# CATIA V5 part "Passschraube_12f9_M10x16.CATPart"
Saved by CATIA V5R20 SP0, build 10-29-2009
Part number: Passschraube_12f9_M10x30
Bounding box of the stored display mesh (mm): x -9 to 9, y -8.998 to 8.998, z -55.4 to 0
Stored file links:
  C:\Users\Andi\Desktop\Plasma\Passschraube_12f9_M10x16.CATPart
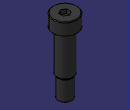
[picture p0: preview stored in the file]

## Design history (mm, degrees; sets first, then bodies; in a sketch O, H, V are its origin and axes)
Body1 (main body)
  Sketch1 on zx-plane, origin (0, 0, 0), H (-1, 0, 0), V (0, 0, 1)
    axis line L1 (0, 20.0273) -> (0, -25.5974)
    point P1 (0, 20.0273)
    line L2 (0, 0) -> (9, 0)
    line L3 (9, 0) -> (9, -9)
    line L4 (9, -9) -> (6, -9)
    line L5 (6, -9) -> (6, -39)
    line L6 (6, -39) -> (4.25, -39)
    line L7 (4.25, -39) -> (4.25, -40.5)
    line L8 (4.25, -40.5) -> (5, -40.5)
    line L9 (5, -40.5) -> (5, -55.4)
    line L10 (5, -55.4) -> (0, -55.4)
    point P11 (0, -55.4)
    length L5 = 30
    distance L6 L10 = 16.4
    distance L9 L1 = 5
    distance L5 L1 = 6
    length L3 = 9
    length L2 = 9
    length L7 = 1.5
    length L6 = 1.75
    coincidence: P1 V, P11 L1
    vertical: L1 V, L3 V, L5 V, L7 V, L9 V
    horizontal: L2 H, L4 H, L6 H, L8 H, L10 H
  Shaft1: profile Sketch1, axis Sketch1.L1, angle 360
  Chamfer1: length 0.5, angle 45, on edge [face of Shaft1 | face of Shaft1]
  Fillet1: radius 0.5, on edge [face of Shaft1 | face of Shaft1]
  Sketch2 on face of Shaft1, origin (0, 0, 0), H (1, 0, 0), V (0, 1, 0)
    point P1 (3, -1.7321)
    point P2 (3, 1.7321)
    point P3 (0, 3.4641)
    point P4 (-3, 1.7321)
    point P5 (-3, -1.7321)
    point P6 (0, -3.4641)
    line L1 (3, -1.7321) -> (3, 1.7321)
    line L2 (3, 1.7321) -> (0, 3.4641)
    line L3 (0, 3.4641) -> (-3, 1.7321)
    line L4 (-3, 1.7321) -> (-3, -1.7321)
    line L5 (-3, -1.7321) -> (0, -3.4641)
    line L6 (0, -3.4641) -> (3, -1.7321)
    construction line L7 (0, 0) -> (1.25, 0)
    construction circle A1 centre (0, 0) radius 3.4641
    construction arc A2 centre (-3, -1.7321) radius 3.4641 from (-3, 1.7321) to (0, -3.4641) cw
    construction arc A3 centre (3, 1.7321) radius 3.4641 from (0, 3.4641) to (3, -1.7321) ccw
    distance L4 L1 = 6
    horizontal: L7 H
    coincidence: A1 P1, A1 P2, A1 P3, A1 P4, A1 P5, A1 P6, A2 O, A3 O
    vertical: L1 V
  Pocket1: profile Sketch2, direction (0, 0, -1), length 3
